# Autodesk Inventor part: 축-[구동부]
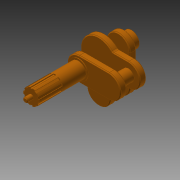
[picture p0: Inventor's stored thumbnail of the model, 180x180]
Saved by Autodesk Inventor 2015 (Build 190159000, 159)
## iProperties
Created: 2017-05
Part Number: 축-[구동부]
Material: 강철, 연강
Document SubType Name: Modeling
Designer: mduedu
Density: 7.86 g/cm^3
Mass: 656.198 g
Surface Area: 242.498 cm^2
Volume: 83.4857 cm^3
Appearance: 주황색
Author: mduedu
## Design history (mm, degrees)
sketch "스케치1"
  geometry: L1 (-38, 15)-(-17.436, 15); L2 (-38, -15)-(-17.436, -15); L3 (-15, -38)-(-15, -17.436); L4 (15, -38)-(15, -17.436); A1 r 23 centre (0, 0) between (-17.436, 15) and (-17.436, -15); A2 r 15 centre (-38, 0) between (-38, 15) and (-38, -15); A3 r 15 centre (0, -38) between (-15, -38) and (15, -38); 1 further point
  constraints: 8 end point, 8 point on circle, 4 tangent, 3 centre point, 2 horizontal, 2 vertical, 1 coincident, 1 horizontal alignment, 1 vertical alignment
  dimensions: "d0" = 46 diameter of A1; "d1" = 30 diameter of A2; "d2" = 30 diameter of A3 (= d1); "d3" = 38 distance of point (0, 0) A2.centre; "d4" = 38 distance of A3.centre point (0, 0)
extrude "돌출1" new body sketch "스케치1" distance "d5" = 8; taper "d6" = 0 deg
fillet "모깎기1" dims "d7" = 3
sketch "스케치2"
  geometry: C1 r 7.5 at (0, -38); A1 r 15 centre (0, -38) between (-15, -38) and (15, -38) reference; 1 further point
  constraints: 1 centre point, 1 coincident
  dimensions: "d8" = 15 diameter of C1
extrude "돌출2" join sketch "스케치2" distance "d9" = 17; taper "d10" = 0 deg
sketch "스케치3"
  geometry: L1 (-15, 0)-(-15, 38); L2 (15, 0)-(15, 38); C1 r 7.5 at (0, 0) reference; A1 r 15 centre (0, 0) between (-15, 0) and (15, 0); A2 r 15 centre (0, 38) between (-15, 38) and (15, 38); 1 further point
  constraints: 4 end point, 4 point on circle, 4 tangent, 2 centre point, 2 coincident
  dimensions: "d11" = 30 diameter of A1; "d12" = 30 diameter of A2 (= d11)
extrude "돌출3" join sketch "스케치3" distance "d13" = 8; taper "d14" = 0 deg
sketch "스케치4"
  geometry: C1 r 12 at (0, 38); A1 r 15 centre (0, 38) between (15, 38) and (-15, 38) reference; 1 further point
  constraints: 1 centre point, 1 coincident
  dimensions: "d15" = 24 diameter of C1
extrude "돌출4" join sketch "스케치4" distance "d16" = 1; taper "d17" = 0 deg
sketch "스케치5"
  geometry: C1 r 10 at (0, 0); 1 further point
  constraints: 1 centre point, 1 coincident
  dimensions: "d18" = 20 diameter of C1
extrude "돌출5" join sketch "스케치5" distance "d19" = 8; taper "d20" = 0 deg
sketch "스케치6"
  geometry: C1 r 7.5 at (38, 0); A1 r 15 centre (38, 0) between (38, -15) and (38, 15) reference; 1 further point
  constraints: 1 centre point, 1 coincident
  dimensions: "d21" = 15 diameter of C1
extrude "돌출6" join sketch "스케치6" distance "d22" = 17; taper "d23" = 0 deg
sketch "스케치7"
  geometry: L1 (-38, 15)-(0, 15); L2 (-38, -15)-(0, -15); C1 r 7.5 at (0, 0) reference; A1 r 15 centre (0, 0) between (0, 15) and (0, -15); A2 r 15 centre (-38, 0) between (-38, 15) and (-38, -15); 1 further point
  constraints: 4 end point, 4 point on circle, 4 tangent, 2 centre point, 2 coincident
  dimensions: "d24" = 30 diameter of A1; "d25" = 30 diameter of A2 (= d24)
extrude "돌출7" join sketch "스케치7" distance "d26" = 8; taper "d27" = 0 deg
sketch "스케치8"
  geometry: C1 r 12 at (-38, 0); 1 further point
  constraints: 1 centre point, 1 coincident
  dimensions: "d28" = 24 diameter of C1
extrude "돌출8" join sketch "스케치8" distance "d29" = 1; taper "d30" = 0 deg
sketch "스케치9"
  geometry: C1 r 10 at (0, 0); 1 further point
  constraints: 1 centre point, 1 coincident
  dimensions: "d31" = 20 diameter of C1
extrude "돌출9" join sketch "스케치9" distance "d32" = 30; taper "d33" = 0 deg
sketch "스케치10"
  geometry: L1 (1.5, 9.887)-(1.5, 8.887); L2 (1.5, 8.887)-(-1.5, 8.887); L3 (-1.5, 8.887)-(-1.5, 9.887); L4 (-4.598, 8.88)-(-4.01, 8.071); L5 (-4.01, 8.071)-(-6.437, 6.308); L6 (-6.437, 6.308)-(-7.025, 7.117); L7 (-8.939, 4.482)-(-7.988, 4.173); L8 (-7.988, 4.173)-(-8.915, 1.32); L9 (-8.915, 1.32)-(-9.866, 1.629); L10 (-9.866, -1.629)-(-8.915, -1.32); L11 (-8.915, -1.32)-(-7.988, -4.173); L12 (-7.988, -4.173)-(-8.939, -4.482); L13 (-7.025, -7.117)-(-6.437, -6.308); L14 (-6.437, -6.308)-(-4.01, -8.071); L15 (-4.01, -8.071)-(-4.598, -8.88); L16 (-1.5, -9.887)-(-1.5, -8.887); L17 (-1.5, -8.887)-(1.5, -8.887); L18 (1.5, -8.887)-(1.5, -9.887); L19 (4.598, -8.88)-(4.01, -8.071); L20 (4.01, -8.071)-(6.437, -6.308); L21 (6.437, -6.308)-(7.025, -7.117); L22 (8.939, -4.482)-(7.988, -4.173); L23 (7.988, -4.173)-(8.915, -1.32); L24 (8.915, -1.32)-(9.866, -1.629); L25 (9.866, 1.629)-(8.915, 1.32); L26 (8.915, 1.32)-(7.988, 4.173); L27 (7.988, 4.173)-(8.939, 4.482); L28 (7.025, 7.117)-(6.437, 6.308); L29 (6.437, 6.308)-(4.01, 8.071); L30 (4.01, 8.071)-(4.598, 8.88); A1 r 10 centre (0, 0) between (1.5, 9.887) and (-1.5, 9.887); A2 r 10 centre (0, 0) between (-4.598, 8.88) and (-7.025, 7.117); A3 r 10 centre (0, 0) between (-8.939, 4.482) and (-9.866, 1.629); A4 r 10 centre (0, 0) between (-9.866, -1.629) and (-8.939, -4.482); A5 r 10 centre (0, 0) between (-7.025, -7.117) and (-4.598, -8.88); A6 r 10 centre (0, 0) between (-1.5, -9.887) and (1.5, -9.887); A7 r 10 centre (0, 0) between (4.598, -8.88) and (7.025, -7.117); A8 r 10 centre (0, 0) between (8.939, -4.482) and (9.866, -1.629); A9 r 10 centre (0, 0) between (9.866, 1.629) and (8.939, 4.482); A10 r 10 centre (0, 0) between (7.025, 7.117) and (4.598, 8.88); 13 further points
  constraints: 60 end point, 20 point on circle, 10 centre point, 3 coincident, 1 horizontal, 1 midpoint, 1 parallel, 1 vertical, 1 vertical alignment, 103 other
  dimensions: "d37" = 3 distance of L1.end L2.end; "d39" = 1 distance of L2.end L3.end; "d42" = 360 deg dimension on A1.centre L1.start (derived)
extrude "돌출10" join sketch "스케치10" distance "d44" = 30; taper "d45" = 0 deg
sketch "스케치11"
  geometry: C1 r 3 at (0, 0); 1 further point
  constraints: 1 centre point, 1 coincident
  dimensions: "d49" = 6 diameter of C1
extrude "돌출11" join sketch "스케치11" distance "d50" = 8; taper "d51" = 0 deg
chamfer "모따기1" distance "d46" = 1; stored, may be unused: second distance "d47" = 2, angle "d48" = 45 deg
node "솔리드1"
node "투영된 루프1"
node "투영된 루프2"
node "투영된 루프3"
